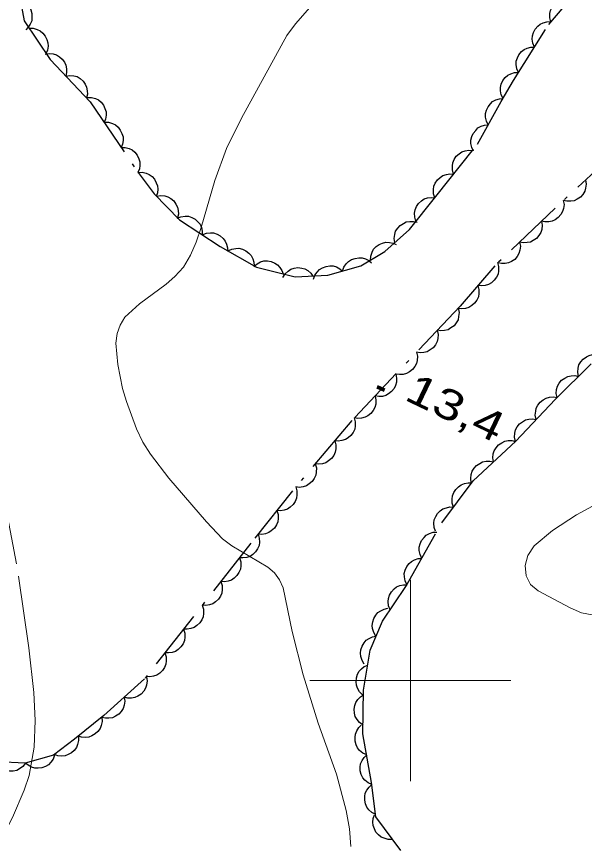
# Model space of a CAD drawing. Extents: x 355726 to 357533, y 5103782 to 5105258.
# Drawn here: x 356180.42 to 356208.66, y 5104891.9 to 5104933 of the extents above; entities that cross this region are included whole.
import ezdxf

# ---------------------------------------------------------------- set-up
doc = ezdxf.new("R2010")
doc.units = 0
doc.header["$LTSCALE"] = 0.6
doc.linetypes.add('DOT_DASHED', pattern=[7.7, 5, -1.2, 0.3, -1.2])
doc.linetypes.add('LONG_DASHED', pattern=[7.5, 6, -1.5])
for name, color, linetype, lineweight in [('2', 7, 'LONG_DASHED', 13), ('3', 7, 'Continuous', 140), ('44', 7, 'Continuous', 25), ('61', 7, 'Continuous', 13)]:
    doc.layers.add(name, color=color, linetype=linetype, lineweight=lineweight)

msp = doc.modelspace()

# ---------------------------------------------------------------- linework, layer by layer
at = {"layer": '2', "linetype": 'Continuous'}
for points in [[(356197.05, 5104891.75), (356196.97, 5104892.63), (356196.81, 5104893.54), (356196.33, 5104895.34), (356195.42, 5104897.88), (356194.68, 5104900.29), (356194.13, 5104902.43), (356193.68, 5104904.61), (356193.5, 5104905.01), (356193.25, 5104905.36), (356192.91, 5104905.63), (356191.12, 5104906.69), (356190.67, 5104907.04), (356189.86, 5104907.88), (356188, 5104910.05), (356187.08, 5104911.25), (356186.7, 5104911.84), (356186.39, 5104912.51), (356185.89, 5104913.86), (356185.7, 5104914.51), (356185.46, 5104915.7), (356185.36, 5104916.76), (356185.42, 5104917.24), (356185.57, 5104917.66), (356185.8, 5104918.05), (356186.54, 5104918.72), (356187.86, 5104919.69), (356188.3, 5104920.08), (356188.73, 5104920.54), (356189.07, 5104921.13), (356189.36, 5104921.78), (356189.61, 5104922.51), (356190.29, 5104924.84), (356190.87, 5104926.43), (356191.6, 5104927.95), (356193.86, 5104932.05), (356194.29, 5104932.63), (356196.06, 5104934.67)], [(356211.25, 5104909.86), (356208.26, 5104908.24), (356207.07, 5104907.46), (356206.15, 5104906.69), (356205.84, 5104906.22), (356205.71, 5104905.71), (356205.76, 5104905.2), (356205.97, 5104904.78), (356206.35, 5104904.45), (356207.94, 5104903.61), (356208.51, 5104903.36), (356209.12, 5104903.25)]]:
    msp.add_lwpolyline(points, dxfattribs=at)
at = {"layer": '2'}
msp.add_lwpolyline([(356179.91, 5104892.59), (356180.23, 5104893.19), (356180.8, 5104894.55), (356181.05, 5104895.28), (356181.3, 5104896.69), (356181.35, 5104898.01), (356181.28, 5104899.4), (356181.04, 5104901.63), (356180.43, 5104905.8), (356179.92, 5104908.42), (356179.56, 5104910.87), (356178.76, 5104915.62), (356177.55, 5104920.58), (356176.42, 5104923.86), (356176.25, 5104924.2), (356175.24, 5104925.51), (356174.84, 5104926.28), (356174.4, 5104927.78), (356174.18, 5104928.34), (356173.03, 5104930.71), (356172.8, 5104931.32), (356172.48, 5104932.59), (356172.38, 5104933.26)], dxfattribs=at)
at = {"layer": '3'}
msp.add_line((356198.35, 5104914.6), (356198.71, 5104914.43), dxfattribs=at)
at = {"layer": '44', "linetype": 'DOT_DASHED'}
for points in [[(356180.56, 5104934.11), (356180.8, 5104932.78), (356182.1, 5104930.86), (356184.09, 5104928.76), (356186.47, 5104925.24), (356187.27, 5104924.19), (356188.52, 5104922.9), (356190.55, 5104921.56), (356192.36, 5104920.54), (356194.27, 5104920.06), (356195.9, 5104920.14), (356197.54, 5104920.6), (356198.74, 5104921.32), (356199.95, 5104922.42), (356201.27, 5104924.06), (356203.34, 5104926.66), (356204.52, 5104928.77), (356205.12, 5104929.82), (356206.88, 5104932.6), (356208.6, 5104934.61)], [(356210.53, 5104926.56), (356207.2, 5104923.48), (356204.2, 5104920.61), (356202.48, 5104918.61), (356197.09, 5104912.92), (356194.14, 5104909.43), (356192.07, 5104906.82), (356186.79, 5104900.09), (356184.76, 5104898.26), (356183.31, 5104897.09), (356182.27, 5104896.29), (356180.86, 5104895.9), (356178.93, 5104895.99)], [(356199.52, 5104891.55), (356198.29, 5104893.23), (356198.07, 5104894.94), (356197.64, 5104897.36), (356197.67, 5104899.52), (356198, 5104901.51), (356198.61, 5104902.95), (356199.78, 5104904.67), (356201.56, 5104907.83), (356203.13, 5104909.92), (356205.24, 5104911.9), (356207.2, 5104913.97), (356208.99, 5104915.74)]]:
    msp.add_lwpolyline(points, dxfattribs=at)
at = {"layer": '44'}
for points in [[(356180.61, 5104933.82), (356180.8, 5104933.73), (356180.96, 5104933.6), (356181.07, 5104933.48), (356181.14, 5104933.32), (356181.19, 5104933.14), (356181.19, 5104932.95), (356181.18, 5104932.78), (356181.11, 5104932.62), (356181.01, 5104932.47), (356180.88, 5104932.34)], [(356206.99, 5104932.73), (356206.94, 5104932.93), (356206.94, 5104933.14), (356206.97, 5104933.3), (356207.05, 5104933.46), (356207.15, 5104933.61), (356207.3, 5104933.73), (356207.44, 5104933.82), (356207.61, 5104933.87), (356207.79, 5104933.89), (356207.97, 5104933.87)], [(356206.17, 5104931.48), (356206.09, 5104931.67), (356206.06, 5104931.87), (356206.07, 5104932.04), (356206.12, 5104932.21), (356206.2, 5104932.37), (356206.33, 5104932.51), (356206.45, 5104932.62), (356206.61, 5104932.69), (356206.79, 5104932.74), (356206.97, 5104932.75)], [(356181.05, 5104932.41), (356181.26, 5104932.41), (356181.45, 5104932.35), (356181.6, 5104932.28), (356181.74, 5104932.17), (356181.85, 5104932.02), (356181.93, 5104931.85), (356181.98, 5104931.69), (356181.99, 5104931.52), (356181.96, 5104931.33), (356181.89, 5104931.17)], [(356205.37, 5104930.21), (356205.29, 5104930.4), (356205.26, 5104930.61), (356205.26, 5104930.77), (356205.32, 5104930.94), (356205.4, 5104931.1), (356205.53, 5104931.25), (356205.65, 5104931.35), (356205.81, 5104931.43), (356205.99, 5104931.47), (356206.17, 5104931.48)], [(356181.84, 5104931.13), (356182.05, 5104931.16), (356182.25, 5104931.14), (356182.41, 5104931.09), (356182.56, 5104931), (356182.7, 5104930.88), (356182.81, 5104930.72), (356182.88, 5104930.58), (356182.91, 5104930.4), (356182.91, 5104930.22), (356182.88, 5104930.04)], [(356182.88, 5104930.04), (356183.08, 5104930.07), (356183.28, 5104930.05), (356183.44, 5104930.01), (356183.59, 5104929.91), (356183.73, 5104929.79), (356183.84, 5104929.63), (356183.91, 5104929.49), (356183.94, 5104929.31), (356183.95, 5104929.13), (356183.91, 5104928.95)], [(356204.61, 5104928.92), (356204.51, 5104929.11), (356204.48, 5104929.31), (356204.48, 5104929.47), (356204.52, 5104929.64), (356204.6, 5104929.81), (356204.72, 5104929.96), (356204.84, 5104930.08), (356204.99, 5104930.15), (356205.17, 5104930.21), (356205.35, 5104930.22)], [(356183.94, 5104928.98), (356184.15, 5104928.98), (356184.35, 5104928.92), (356184.5, 5104928.85), (356184.63, 5104928.74), (356184.74, 5104928.59), (356184.82, 5104928.42), (356184.88, 5104928.26), (356184.88, 5104928.09), (356184.85, 5104927.9), (356184.78, 5104927.74)], [(356203.87, 5104927.61), (356203.78, 5104927.8), (356203.74, 5104928), (356203.74, 5104928.17), (356203.78, 5104928.34), (356203.86, 5104928.5), (356203.98, 5104928.65), (356204.09, 5104928.77), (356204.25, 5104928.85), (356204.43, 5104928.91), (356204.61, 5104928.92)], [(356184.78, 5104927.74), (356184.99, 5104927.74), (356185.19, 5104927.68), (356185.34, 5104927.61), (356185.47, 5104927.49), (356185.58, 5104927.35), (356185.66, 5104927.18), (356185.72, 5104927.02), (356185.72, 5104926.84), (356185.69, 5104926.66), (356185.62, 5104926.49)], [(356203.14, 5104926.3), (356203.05, 5104926.49), (356203.01, 5104926.69), (356203.01, 5104926.86), (356203.05, 5104927.03), (356203.13, 5104927.19), (356203.25, 5104927.34), (356203.36, 5104927.46), (356203.52, 5104927.54), (356203.69, 5104927.6), (356203.87, 5104927.61)], [(356185.62, 5104926.49), (356185.83, 5104926.49), (356186.03, 5104926.43), (356186.18, 5104926.37), (356186.31, 5104926.25), (356186.42, 5104926.11), (356186.5, 5104925.93), (356186.56, 5104925.78), (356186.56, 5104925.6), (356186.53, 5104925.42), (356186.46, 5104925.25)], [(356202.15, 5104925.17), (356202.09, 5104925.37), (356202.09, 5104925.57), (356202.11, 5104925.73), (356202.18, 5104925.89), (356202.28, 5104926.05), (356202.42, 5104926.18), (356202.56, 5104926.27), (356202.72, 5104926.33), (356202.91, 5104926.35), (356203.09, 5104926.34)], [(356186.46, 5104925.25), (356186.67, 5104925.26), (356186.87, 5104925.21), (356187.02, 5104925.15), (356187.16, 5104925.05), (356187.28, 5104924.91), (356187.37, 5104924.74), (356187.43, 5104924.59), (356187.45, 5104924.41), (356187.43, 5104924.23), (356187.37, 5104924.06)], [(356201.22, 5104923.99), (356201.15, 5104924.19), (356201.15, 5104924.4), (356201.17, 5104924.56), (356201.24, 5104924.72), (356201.35, 5104924.88), (356201.49, 5104925), (356201.62, 5104925.1), (356201.79, 5104925.15), (356201.97, 5104925.18), (356202.15, 5104925.17)], [(356208.71, 5104924.88), (356208.74, 5104924.67), (356208.71, 5104924.47), (356208.67, 5104924.31), (356208.57, 5104924.16), (356208.45, 5104924.02), (356208.29, 5104923.92), (356208.14, 5104923.84), (356207.97, 5104923.82), (356207.78, 5104923.82), (356207.61, 5104923.86)], [(356187.39, 5104924.07), (356187.59, 5104924.11), (356187.79, 5104924.08), (356187.95, 5104924.04), (356188.1, 5104923.95), (356188.24, 5104923.83), (356188.35, 5104923.67), (356188.43, 5104923.53), (356188.46, 5104923.35), (356188.47, 5104923.17), (356188.43, 5104922.99)], [(356200.28, 5104922.83), (356200.22, 5104923.03), (356200.21, 5104923.23), (356200.24, 5104923.39), (356200.31, 5104923.55), (356200.41, 5104923.71), (356200.55, 5104923.83), (356200.69, 5104923.93), (356200.85, 5104923.98), (356201.04, 5104924.01), (356201.22, 5104923.99)], [(356207.6, 5104923.86), (356207.64, 5104923.66), (356207.61, 5104923.46), (356207.57, 5104923.3), (356207.48, 5104923.15), (356207.35, 5104923.01), (356207.2, 5104922.9), (356207.05, 5104922.82), (356206.88, 5104922.79), (356206.69, 5104922.79), (356206.52, 5104922.83)], [(356188.41, 5104922.97), (356188.6, 5104923.05), (356188.81, 5104923.07), (356188.97, 5104923.07), (356189.14, 5104923.01), (356189.3, 5104922.92), (356189.44, 5104922.79), (356189.55, 5104922.67), (356189.62, 5104922.51), (356189.66, 5104922.33), (356189.66, 5104922.15)], [(356199.23, 5104921.76), (356199.2, 5104921.97), (356199.23, 5104922.17), (356199.27, 5104922.33), (356199.37, 5104922.48), (356199.49, 5104922.61), (356199.66, 5104922.71), (356199.8, 5104922.79), (356199.97, 5104922.81), (356200.16, 5104922.81), (356200.34, 5104922.77)], [(356206.52, 5104922.83), (356206.55, 5104922.62), (356206.53, 5104922.42), (356206.48, 5104922.26), (356206.39, 5104922.11), (356206.27, 5104921.97), (356206.11, 5104921.86), (356205.97, 5104921.79), (356205.8, 5104921.76), (356205.61, 5104921.75), (356205.43, 5104921.79)], [(356189.66, 5104922.15), (356189.86, 5104922.23), (356190.06, 5104922.24), (356190.22, 5104922.24), (356190.39, 5104922.18), (356190.55, 5104922.09), (356190.69, 5104921.96), (356190.8, 5104921.84), (356190.87, 5104921.68), (356190.91, 5104921.5), (356190.92, 5104921.32)], [(356198.02, 5104920.89), (356198.03, 5104921.09), (356198.1, 5104921.29), (356198.17, 5104921.43), (356198.3, 5104921.56), (356198.45, 5104921.67), (356198.62, 5104921.74), (356198.78, 5104921.78), (356198.96, 5104921.77), (356199.14, 5104921.73), (356199.3, 5104921.66)], [(356205.43, 5104921.79), (356205.47, 5104921.58), (356205.44, 5104921.38), (356205.4, 5104921.22), (356205.31, 5104921.07), (356205.19, 5104920.93), (356205.03, 5104920.83), (356204.88, 5104920.75), (356204.71, 5104920.72), (356204.53, 5104920.72), (356204.35, 5104920.75)], [(356190.93, 5104921.35), (356191.12, 5104921.44), (356191.32, 5104921.47), (356191.48, 5104921.48), (356191.65, 5104921.43), (356191.82, 5104921.36), (356191.97, 5104921.24), (356192.09, 5104921.12), (356192.17, 5104920.96), (356192.22, 5104920.79), (356192.24, 5104920.61)], [(356196.63, 5104920.34), (356196.7, 5104920.54), (356196.81, 5104920.71), (356196.93, 5104920.83), (356197.08, 5104920.92), (356197.25, 5104920.98), (356197.44, 5104921), (356197.6, 5104921), (356197.77, 5104920.95), (356197.94, 5104920.87), (356198.07, 5104920.75)], [(356192.22, 5104920.57), (356192.38, 5104920.71), (356192.56, 5104920.8), (356192.72, 5104920.85), (356192.9, 5104920.85), (356193.08, 5104920.82), (356193.26, 5104920.74), (356193.4, 5104920.66), (356193.52, 5104920.53), (356193.62, 5104920.38), (356193.68, 5104920.21)], [(356193.66, 5104920.03), (356193.77, 5104920.21), (356193.92, 5104920.34), (356194.06, 5104920.44), (356194.23, 5104920.49), (356194.41, 5104920.52), (356194.6, 5104920.49), (356194.76, 5104920.46), (356194.91, 5104920.37), (356195.05, 5104920.25), (356195.16, 5104920.1)], [(356195.19, 5104919.94), (356195.25, 5104920.14), (356195.37, 5104920.3), (356195.48, 5104920.42), (356195.63, 5104920.51), (356195.81, 5104920.58), (356196, 5104920.6), (356196.16, 5104920.6), (356196.33, 5104920.55), (356196.49, 5104920.46), (356196.63, 5104920.34)], [(356204.34, 5104920.77), (356204.39, 5104920.57), (356204.38, 5104920.36), (356204.36, 5104920.2), (356204.28, 5104920.04), (356204.17, 5104919.89), (356204.03, 5104919.77), (356203.89, 5104919.68), (356203.72, 5104919.63), (356203.54, 5104919.61), (356203.36, 5104919.63)], [(356203.36, 5104919.63), (356203.41, 5104919.43), (356203.41, 5104919.23), (356203.38, 5104919.06), (356203.3, 5104918.9), (356203.19, 5104918.75), (356203.05, 5104918.63), (356202.91, 5104918.54), (356202.74, 5104918.49), (356202.56, 5104918.47), (356202.38, 5104918.49)], [(356202.37, 5104918.5), (356202.42, 5104918.29), (356202.4, 5104918.09), (356202.37, 5104917.93), (356202.28, 5104917.78), (356202.17, 5104917.63), (356202.02, 5104917.52), (356201.88, 5104917.43), (356201.7, 5104917.39), (356201.52, 5104917.38), (356201.34, 5104917.41)], [(356201.34, 5104917.41), (356201.39, 5104917.2), (356201.37, 5104917), (356201.34, 5104916.84), (356201.25, 5104916.69), (356201.14, 5104916.54), (356200.98, 5104916.43), (356200.84, 5104916.34), (356200.67, 5104916.3), (356200.49, 5104916.29), (356200.31, 5104916.32)], [(356200.31, 5104916.32), (356200.36, 5104916.12), (356200.34, 5104915.91), (356200.31, 5104915.75), (356200.22, 5104915.6), (356200.11, 5104915.45), (356199.95, 5104915.34), (356199.81, 5104915.25), (356199.64, 5104915.21), (356199.46, 5104915.2), (356199.28, 5104915.23)], [(356208.36, 5104915.11), (356208.32, 5104915.32), (356208.34, 5104915.52), (356208.38, 5104915.68), (356208.47, 5104915.83), (356208.59, 5104915.97), (356208.75, 5104916.08), (356208.89, 5104916.16), (356209.06, 5104916.2), (356209.25, 5104916.2), (356209.42, 5104916.17)], [(356199.28, 5104915.23), (356199.32, 5104915.03), (356199.31, 5104914.82), (356199.27, 5104914.66), (356199.19, 5104914.51), (356199.07, 5104914.36), (356198.92, 5104914.25), (356198.78, 5104914.16), (356198.61, 5104914.12), (356198.43, 5104914.11), (356198.25, 5104914.14)], [(356207.29, 5104914.06), (356207.25, 5104914.26), (356207.27, 5104914.47), (356207.31, 5104914.63), (356207.4, 5104914.78), (356207.52, 5104914.92), (356207.68, 5104915.03), (356207.82, 5104915.11), (356207.99, 5104915.14), (356208.18, 5104915.15), (356208.36, 5104915.11)], [(356198.25, 5104914.14), (356198.29, 5104913.94), (356198.28, 5104913.74), (356198.24, 5104913.57), (356198.16, 5104913.42), (356198.04, 5104913.27), (356197.89, 5104913.16), (356197.75, 5104913.08), (356197.58, 5104913.04), (356197.39, 5104913.02), (356197.22, 5104913.05)], [(356206.25, 5104912.97), (356206.21, 5104913.18), (356206.23, 5104913.38), (356206.26, 5104913.54), (356206.34, 5104913.69), (356206.46, 5104913.84), (356206.61, 5104913.95), (356206.75, 5104914.04), (356206.92, 5104914.08), (356207.11, 5104914.09), (356207.29, 5104914.06)], [(356197.21, 5104913.06), (356197.26, 5104912.86), (356197.26, 5104912.66), (356197.24, 5104912.49), (356197.16, 5104912.33), (356197.05, 5104912.18), (356196.91, 5104912.06), (356196.77, 5104911.97), (356196.6, 5104911.92), (356196.42, 5104911.9), (356196.24, 5104911.91)], [(356205.22, 5104911.88), (356205.18, 5104912.09), (356205.19, 5104912.29), (356205.23, 5104912.45), (356205.31, 5104912.61), (356205.43, 5104912.75), (356205.58, 5104912.86), (356205.72, 5104912.95), (356205.89, 5104912.99), (356206.08, 5104913), (356206.25, 5104912.97)], [(356196.24, 5104911.91), (356196.3, 5104911.71), (356196.29, 5104911.51), (356196.27, 5104911.35), (356196.19, 5104911.19), (356196.08, 5104911.04), (356195.94, 5104910.91), (356195.8, 5104910.82), (356195.63, 5104910.77), (356195.45, 5104910.75), (356195.27, 5104910.77)], [(356204.13, 5104910.86), (356204.1, 5104911.06), (356204.12, 5104911.26), (356204.17, 5104911.42), (356204.26, 5104911.57), (356204.38, 5104911.71), (356204.54, 5104911.82), (356204.69, 5104911.89), (356204.86, 5104911.92), (356205.05, 5104911.92), (356205.22, 5104911.88)], [(356195.27, 5104910.77), (356195.33, 5104910.57), (356195.32, 5104910.36), (356195.3, 5104910.2), (356195.22, 5104910.04), (356195.12, 5104909.89), (356194.97, 5104909.77), (356194.84, 5104909.68), (356194.67, 5104909.63), (356194.48, 5104909.6), (356194.3, 5104909.62)], [(356203.03, 5104909.83), (356203, 5104910.04), (356203.03, 5104910.24), (356203.07, 5104910.4), (356203.17, 5104910.55), (356203.29, 5104910.68), (356203.45, 5104910.79), (356203.59, 5104910.87), (356203.77, 5104910.9), (356203.95, 5104910.9), (356204.13, 5104910.86)], [(356194.3, 5104909.63), (356194.36, 5104909.43), (356194.36, 5104909.23), (356194.34, 5104909.06), (356194.27, 5104908.9), (356194.17, 5104908.75), (356194.03, 5104908.62), (356193.9, 5104908.52), (356193.73, 5104908.47), (356193.54, 5104908.44), (356193.36, 5104908.45)], [(356202.15, 5104908.62), (356202.08, 5104908.81), (356202.08, 5104909.02), (356202.09, 5104909.18), (356202.16, 5104909.34), (356202.26, 5104909.5), (356202.39, 5104909.63), (356202.52, 5104909.73), (356202.69, 5104909.79), (356202.87, 5104909.82), (356203.05, 5104909.82)], [(356201.25, 5104907.42), (356201.18, 5104907.61), (356201.17, 5104907.82), (356201.19, 5104907.98), (356201.26, 5104908.15), (356201.35, 5104908.3), (356201.49, 5104908.43), (356201.62, 5104908.53), (356201.79, 5104908.59), (356201.97, 5104908.63), (356202.15, 5104908.62)], [(356193.36, 5104908.45), (356193.43, 5104908.25), (356193.43, 5104908.05), (356193.41, 5104907.89), (356193.34, 5104907.73), (356193.24, 5104907.57), (356193.09, 5104907.44), (356192.96, 5104907.35), (356192.8, 5104907.29), (356192.61, 5104907.26), (356192.43, 5104907.28)], [(356200.57, 5104906.07), (356200.48, 5104906.26), (356200.44, 5104906.46), (356200.44, 5104906.63), (356200.48, 5104906.8), (356200.56, 5104906.96), (356200.68, 5104907.11), (356200.79, 5104907.23), (356200.95, 5104907.31), (356201.13, 5104907.37), (356201.31, 5104907.38)], [(356192.43, 5104907.28), (356192.49, 5104907.08), (356192.5, 5104906.88), (356192.48, 5104906.71), (356192.41, 5104906.55), (356192.31, 5104906.4), (356192.17, 5104906.27), (356192.03, 5104906.17), (356191.87, 5104906.12), (356191.68, 5104906.09), (356191.5, 5104906.1)], [(356191.5, 5104906.1), (356191.57, 5104905.9), (356191.57, 5104905.7), (356191.55, 5104905.53), (356191.48, 5104905.37), (356191.38, 5104905.22), (356191.24, 5104905.09), (356191.11, 5104904.99), (356190.94, 5104904.94), (356190.76, 5104904.91), (356190.58, 5104904.92)], [(356199.83, 5104904.77), (356199.74, 5104904.95), (356199.71, 5104905.15), (356199.7, 5104905.32), (356199.75, 5104905.49), (356199.82, 5104905.66), (356199.94, 5104905.81), (356200.06, 5104905.92), (356200.21, 5104906), (356200.39, 5104906.06), (356200.57, 5104906.07)], [(356190.58, 5104904.92), (356190.64, 5104904.72), (356190.65, 5104904.52), (356190.63, 5104904.35), (356190.56, 5104904.19), (356190.46, 5104904.04), (356190.31, 5104903.91), (356190.18, 5104903.81), (356190.02, 5104903.76), (356189.83, 5104903.73), (356189.65, 5104903.74)], [(356199, 5104903.52), (356198.92, 5104903.72), (356198.9, 5104903.92), (356198.91, 5104904.08), (356198.97, 5104904.25), (356199.06, 5104904.41), (356199.19, 5104904.55), (356199.32, 5104904.65), (356199.48, 5104904.72), (356199.66, 5104904.76), (356199.84, 5104904.76)], [(356189.65, 5104903.74), (356189.72, 5104903.54), (356189.72, 5104903.34), (356189.7, 5104903.17), (356189.63, 5104903.01), (356189.53, 5104902.86), (356189.39, 5104902.73), (356189.26, 5104902.63), (356189.09, 5104902.58), (356188.91, 5104902.55), (356188.73, 5104902.56)], [(356198.29, 5104902.2), (356198.18, 5104902.38), (356198.12, 5104902.58), (356198.1, 5104902.74), (356198.13, 5104902.91), (356198.18, 5104903.09), (356198.29, 5104903.25), (356198.39, 5104903.38), (356198.53, 5104903.47), (356198.7, 5104903.55), (356198.88, 5104903.59)], [(356188.73, 5104902.56), (356188.79, 5104902.36), (356188.79, 5104902.16), (356188.77, 5104901.99), (356188.71, 5104901.83), (356188.6, 5104901.68), (356188.46, 5104901.55), (356188.33, 5104901.45), (356188.16, 5104901.4), (356187.98, 5104901.37), (356187.8, 5104901.38)], [(356197.71, 5104900.82), (356197.6, 5104901), (356197.54, 5104901.19), (356197.52, 5104901.36), (356197.54, 5104901.53), (356197.6, 5104901.71), (356197.7, 5104901.87), (356197.8, 5104902), (356197.95, 5104902.09), (356198.12, 5104902.17), (356198.29, 5104902.2)], [(356187.8, 5104901.38), (356187.86, 5104901.18), (356187.87, 5104900.98), (356187.85, 5104900.81), (356187.78, 5104900.65), (356187.68, 5104900.5), (356187.54, 5104900.37), (356187.4, 5104900.27), (356187.24, 5104900.22), (356187.05, 5104900.19), (356186.88, 5104900.2)], [(356197.63, 5104899.29), (356197.48, 5104899.44), (356197.38, 5104899.62), (356197.32, 5104899.77), (356197.3, 5104899.94), (356197.32, 5104900.13), (356197.38, 5104900.31), (356197.45, 5104900.46), (356197.57, 5104900.59), (356197.71, 5104900.7), (356197.88, 5104900.77)], [(356186.89, 5104900.18), (356186.92, 5104899.98), (356186.89, 5104899.77), (356186.84, 5104899.62), (356186.75, 5104899.47), (356186.62, 5104899.33), (356186.46, 5104899.23), (356186.31, 5104899.16), (356186.14, 5104899.13), (356185.95, 5104899.13), (356185.78, 5104899.18)], [(356185.78, 5104899.18), (356185.81, 5104898.97), (356185.78, 5104898.77), (356185.73, 5104898.61), (356185.63, 5104898.46), (356185.51, 5104898.33), (356185.34, 5104898.23), (356185.2, 5104898.15), (356185.02, 5104898.13), (356184.84, 5104898.13), (356184.66, 5104898.17)], [(356197.65, 5104897.79), (356197.47, 5104897.91), (356197.35, 5104898.07), (356197.26, 5104898.21), (356197.22, 5104898.38), (356197.21, 5104898.57), (356197.24, 5104898.76), (356197.29, 5104898.91), (356197.39, 5104899.06), (356197.52, 5104899.19), (356197.67, 5104899.29)], [(356184.66, 5104898.18), (356184.68, 5104897.97), (356184.63, 5104897.77), (356184.58, 5104897.62), (356184.47, 5104897.47), (356184.34, 5104897.35), (356184.17, 5104897.25), (356184.02, 5104897.19), (356183.85, 5104897.17), (356183.66, 5104897.18), (356183.49, 5104897.24)], [(356197.83, 5104896.31), (356197.64, 5104896.39), (356197.48, 5104896.53), (356197.37, 5104896.65), (356197.3, 5104896.81), (356197.25, 5104896.99), (356197.25, 5104897.18), (356197.27, 5104897.34), (356197.34, 5104897.5), (356197.44, 5104897.66), (356197.56, 5104897.79)], [(356183.5, 5104897.23), (356183.51, 5104897.02), (356183.46, 5104896.83), (356183.4, 5104896.67), (356183.29, 5104896.53), (356183.16, 5104896.41), (356182.99, 5104896.32), (356182.84, 5104896.26), (356182.66, 5104896.24), (356182.48, 5104896.26), (356182.31, 5104896.32)], [(356182.31, 5104896.3), (356182.25, 5104896.1), (356182.13, 5104895.94), (356182.02, 5104895.82), (356181.86, 5104895.73), (356181.69, 5104895.67), (356181.5, 5104895.65), (356181.34, 5104895.65), (356181.17, 5104895.7), (356181.01, 5104895.79), (356180.87, 5104895.9)], [(356198.09, 5104894.83), (356197.9, 5104894.92), (356197.74, 5104895.05), (356197.64, 5104895.17), (356197.56, 5104895.33), (356197.51, 5104895.51), (356197.51, 5104895.7), (356197.53, 5104895.87), (356197.6, 5104896.03), (356197.7, 5104896.18), (356197.83, 5104896.31)], [(356180.87, 5104895.9), (356180.74, 5104895.73), (356180.58, 5104895.61), (356180.44, 5104895.53), (356180.26, 5104895.5), (356180.08, 5104895.49), (356179.89, 5104895.53), (356179.74, 5104895.58), (356179.59, 5104895.68), (356179.46, 5104895.82), (356179.37, 5104895.97)], [(356198.28, 5104893.34), (356198.09, 5104893.44), (356197.94, 5104893.58), (356197.84, 5104893.71), (356197.77, 5104893.87), (356197.73, 5104894.05), (356197.74, 5104894.24), (356197.76, 5104894.4), (356197.84, 5104894.56), (356197.95, 5104894.71), (356198.08, 5104894.83)], [(356199.11, 5104892.11), (356198.9, 5104892.1), (356198.7, 5104892.16), (356198.55, 5104892.22), (356198.41, 5104892.33), (356198.29, 5104892.47), (356198.21, 5104892.64), (356198.15, 5104892.79), (356198.14, 5104892.97), (356198.16, 5104893.15), (356198.22, 5104893.32)]]:
    msp.add_lwpolyline(points, dxfattribs=at)
at = {"layer": '61'}
for p, q in [((356200, 5104895), (356200, 5104905)), ((356195, 5104900), (356205, 5104900))]:
    msp.add_line(p, q, dxfattribs=at)

# ---------------------------------------------------------------- texts
at = {"layer": '3', "width": 1.3}
msp.add_text('13,4   ', height=1.5, rotation=334.423, dxfattribs=at).set_placement((356199.64, 5104913.98))

doc.saveas('drawing.dxf')
